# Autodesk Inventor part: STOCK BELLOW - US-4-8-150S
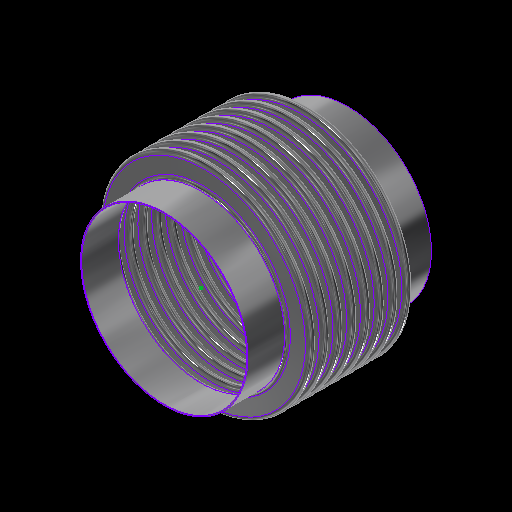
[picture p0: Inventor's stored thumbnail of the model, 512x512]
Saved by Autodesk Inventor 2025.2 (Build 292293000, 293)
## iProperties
Category: 22 GA (0.030 THICK)
RuleStatus: InUse
Created: 2024-01
Part Number: STOCK BELLOW - US-4-8-150S
Project: =STOCK BELLOWS: <Stock Number><SFILL>
Material: ASTM A240-304
Description: =STOCK BELLOWS: <Stock Number>, <SID_> I.D., <SOD_> O.D., <SPLY_> PLY, <Category>, <SNET_CONS> CONS.<PITCH_><STANGENT_> TANGENT<SFILL>
Document SubType Name: Sheet Metal
Designer: GS
Stock Number: U.S-4-8-150S
Surface Area: 2717.32 cm^2
Volume: 102.9 cm^3
Sheet Metal Rule: Default
Appearance: STAINLESS STEEL
Mass: 829.096 g
Density: 8.05729 g/cm^3
THK: 0.036
ID: 3.500
OD: 4.250
CONS_: 2
PITCH: 0.500
TANGENT: 0.500
BELLOWS_UPSET: 0.000
d79: 1.000
d82: 1.000
d83: 26.000
d84: 24.000
d174: 8
d214: 8
STHK_: 0.030
SID_: 4.500
SOD_: 5.750
SPITCH_: 0.375
STANGENT__: 1.000
SBELLOWS_UPSET_: 0.000
SDIFF_TAN: 1.000
d252: 2
d275: 2
d287: 0.050
d289: 0.500
d290: 0.000
SOD_NECK: 4 9/16
PLY: 1
PSET: 4.178
PBAR: 1.035
COUNTER: 1.500
NET_TUBE: 3.071
CONS: 2
S_CONS: 0
NET_CONS: 2
ID_M: 88.90 mm
OD_M: 107.95 mm
THK_M: 0.91 mm
ID_U: 3.500 in
OD_U: 4.250 in
THK_U: 0.036 in
TANGENT2: 0.500
TAN_TO_TAN: 1.000 in
d80: 2.571
d81: 10
SID: 2.375
SCONS_: 8
SPITCH: 0.250
STANGENT_: 1.000
SBELLOWS_UPSET: 0.000
SNET_CONS: 8
SS_CONS: 0
SCONS: 8
d190: 8
d191: 1
d192: 1
d193: 8
d194: 0
SIZE: 4.00
PRESSURE: 150
d230: 8
STANGENT: 4.000
SPLY_: 1
d233: 8
d234: 0
d263: 2
d265: 1
d268: 2
d269: 0
d286: 2
d288: 1
d291: 2
d292: 0
SREROLL: 0.750
BLETP: 0.000 ul
PRES_Copy: 85
MATTABLE: 20 GA (0.036 THICK)
PART_NUMBER: U.S-4-8-150S
PITCH_: =, <SPITCH_> PITCH,
CFILL: .
SFILL: .
MESH: ,
COMP: 0.7
EXT: 0.35
LAT: 0.13
ANG: 573
ASR: 1224
LSR: 4822
ANSR: 63
PRES: 150
COMPM: 7.0
EXTM: 3.5
LATM: 1.30
ASRM: 214.359
PRESM: 10.342
LSRM: 844.477
ANSRM: 11.033
TEMPMIN: 20
TEMPMAX: 800
TEMPMINM: -7
TEMPMAXM: 427
WEIGHTM: 0.829
WEIGHT: 1.828
Author: GS
Keywords: 20 GA (0.036 THICK)
Comments: =STOCK BELLOW - <STOCK NUMBER>
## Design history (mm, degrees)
sketch "Sketch2"
  geometry: L1 (0, -177.245)-(0, 562.856) reference; L2 (45.364, 0)-(44.45, 0); L3 (48.082, -2.718)-(50.343, -2.718); L4 (48.082, -3.632)-(50.343, -3.632); L5 (50.343, -9.982)-(48.082, -9.982); L6 (50.343, -9.068)-(48.082, -9.068); L7 (45.364, -12.7)-(44.45, -12.7); L8 (48.082, 0)-(48.082, -12.7); L9 (50.343, -6.35)-(53.975, -6.35); L10 (44.45, 0)-(44.45, -12.7); L11 (20.376, 102.841)-(20.376, 101.926); L12 (58.262, 457.127)-(58.262, 349.177); L13 (58.262, 444.427)-(58.262, 336.477); L14 (93.133, -58.817)-(93.133, -71.517); L15 (118.746, -66.401)-(118.746, -66.401); L16 (50.343, -9.068)-(50.343, -9.982); L17 (48.082, -9.068)-(48.082, -9.982); L18 (48.082, -9.525)-(50.343, -9.525); L19 (53.975, 0)-(53.975, -12.7); L20 (-50.343, -9.068)-(-50.343, -9.982); L21 (-50.343, -2.718)-(-48.082, -2.718); L22 (-50.343, -3.632)-(-48.082, -3.632); L23 (-48.082, -9.068)-(-50.343, -9.068); L24 (-50.343, -9.525)-(-48.082, -9.525); L25 (-48.082, -9.982)-(-50.343, -9.982); L26 (-48.082, -9.068)-(-48.082, -9.982); L27 (-44.45, 0.653)-(-44.45, -12.047); L28 (-48.082, -6.35)-(-44.45, -6.35); L29 (-50.343, 0.653)-(-50.343, -12.7); L30 (-53.061, 0)-(-53.975, 0); L31 (-53.975, 0)-(-53.975, -12.7); L32 (-53.061, -12.7)-(-53.975, -12.7); A1 r 2.718 centre (48.082, 0) between (45.364, 0) and (48.082, -2.718); A2 r 3.632 centre (48.082, 0) between (44.45, 0) and (48.082, -3.632); A3 r 3.632 centre (50.343, -6.35) between (50.343, -9.982) and (50.343, -2.718); A4 r 2.718 centre (50.343, -6.35) between (50.343, -9.068) and (50.343, -3.632); A5 r 2.718 centre (48.082, -12.7) between (48.082, -9.982) and (45.364, -12.7); A6 r 3.632 centre (48.082, -12.7) between (48.082, -9.068) and (44.45, -12.7); A7 r 3.175 centre (50.343, -6.35) between (50.343, -9.525) and (53.518, -6.35); A8 r 3.175 centre (48.082, -12.7) between (48.082, -9.525) and (44.907, -12.7); A9 r 2.718 centre (-50.343, -12.7) between (-50.343, -9.982) and (-53.061, -12.7); A10 r 2.718 centre (-48.082, -6.35) between (-48.082, -9.068) and (-48.082, -3.632); A11 r 3.175 centre (-48.082, -6.35) between (-48.082, -9.525) and (-44.907, -6.35); A12 r 3.632 centre (-48.082, -6.35) between (-48.082, -9.982) and (-48.082, -2.718); A13 r 3.175 centre (-50.343, -12.7) between (-50.343, -9.525) and (-53.518, -12.7); A14 r 3.632 centre (-50.343, -12.7) between (-50.343, -9.068) and (-53.975, -12.7); A15 r 2.718 centre (-50.343, 0) between (-53.061, 0) and (-50.343, -2.718); A16 r 3.632 centre (-50.343, 0) between (-53.975, 0) and (-50.343, -3.632); 10 further points
  constraints: 62 end point, 38 point on circle, 20 tangent, 16 centre point, 12 parallel, 9 midpoint, 7 vertical, 6 coincident, 6 concentric, 6 point on line, 4 equal radius, 4 perpendicular, 3 horizontal, 1 collinear, 1 horizontal alignment, 10 other
  dimensions: "THK" = 0.9144 distance of L11.start L11.end; "ID" = 88.9 distance of L11.end point (20.376, 13.026); "OD" = 107.95 distance of L12.start L12.end; "PITCH" = 12.7 distance of L12.start L13.start; "TANGENT" = 12.7 distance of L14.start L14.end; "BELLOWS_UPSET" = 0 distance of L15.start L15.end; "d43" = 88.9 diameter of L10 L1 (= ID); "d44" = 107.95 diameter of L9.end L1 (= OD); "d45" = 0.9144 distance between parallel lines of L5 L6 (computed from THK, PLY); "d46" = 3.6322 radius of A3 (computed from PITCH, THK, PLY); "UPSET_PITCH" = 12.7 distance of L2.end L7.end (derived); "SIDEWALL_ANGLE" = 360 deg dimension on L3 L9 (derived); "CON_GAP" = 5.4356 distance of point (48.082, -9.068) point (48.082, -3.632) (derived); "TAN1" = 4.98728 dimension on A8 (derived); "TAN2" = 4.98728 dimension on A7 (derived); "LEG1" = 2.2606 distance of L18.start L18.end (derived); "d278" = 0.9144 distance between parallel lines of L25 L23 (derived); "d279" = 3.6322 radius of A12 (derived); "d280" = 12.7 distance of L30.end L31.end (derived); "d281" = 360 deg dimension on L21 L28 (derived); "d282" = 5.4356 distance of point (-50.343, -9.068) point (-50.343, -3.632) (derived); "d283" = 4.98728 dimension on A13 (derived); "d284" = 4.98728 dimension on A11 (derived); "d285" = 2.2606 distance of L24.start L24.end (derived); "d293" = 88.9 diameter of L27 L1 (derived); "d294" = 107.95 diameter of L31 L1 (derived)
  node "Sketch Rectangular Pattern1" dims "d31" = 25.4, "ID" = 88.9
  node "Sketch Rectangular Pattern2" dims "d39" = 25.4, "PITCH" = 12.7
revolve "CONS" stored, may be unused: angle "d48" = 90 deg
node "BELLOW MIDPLANE"
pattern_linear "Rectangular Pattern2" dims "d52" = 12.7 (= UPSET_PITCH)
sketch "Sketch5"
  geometry: C1 r 45.364 at (0, 0) reference; C2 r 44.45 at (0, 0) reference
extrude "TANGENT" new body sketch "Sketch5" distance "d53" = 12.7 (= TANGENT); taper "d54" = 0 deg
revolve "SAMETAN" stored, may be unused: angle "d65" = 90 deg
revolve "DIFFTAN" stored, may be unused: angle "d70" = 90 deg
sketch "Sketch9"
  geometry: L1 (53.319, 0)-(-53.319, 0) reference; L2 (0, -17.78)-(0, 17.78) reference; L3 (38.085, 0)-(-38.085, 0); L4 (38.085, -11.906)-(38.085, 11.906); L5 (25.385, -11.906)-(25.385, 11.906); L6 (13.15, 11.906)-(13.15, -11.906); L7 (-25.385, -11.906)-(-25.385, 11.906); L8 (-38.085, -11.906)-(-38.085, 11.906); L9 (37.291, -11.906)-(37.291, 11.906); L10 (38.085, -11.906)-(37.291, -11.906); L11 (38.085, 11.906)-(37.291, 11.906); L12 (13.546, 11.906)-(12.753, 11.906); L13 (12.753, 11.906)-(12.753, -11.906); L14 (12.753, -11.906)-(13.546, -11.906); L15 (13.546, -11.906)-(13.546, 11.906); L16 (-13.546, 11.906)-(-13.546, -11.906); L17 (-13.15, 11.906)-(-13.15, -11.906); L18 (-13.546, -11.906)-(-12.753, -11.906); L19 (-12.753, -11.906)-(-12.753, 11.906); L20 (-12.753, 11.906)-(-13.546, 11.906); L21 (-38.085, -11.906)-(-37.291, -11.906); L22 (-37.291, -11.906)-(-37.291, 11.906); L23 (-37.291, 11.906)-(-38.085, 11.906); L24 (-38.085, 11.906)-(-38.085, -11.906); L25 (38.085, -0.397)-(-38.085, -0.397); L26 (-38.085, -0.397)-(-38.085, 0.397); L27 (-38.085, 0.397)-(38.085, 0.397); L28 (38.085, 0.397)-(38.085, -0.397); L29 (-38.085, 11.906)-(38.085, 11.906); L30 (38.085, 11.906)-(38.085, 12.7); L31 (38.085, 12.7)-(-38.085, 12.7); L32 (-38.085, 12.7)-(-38.085, 11.906); L33 (38.085, -11.906)-(-38.085, -11.906); L34 (-38.085, -11.906)-(-38.085, -12.7); L35 (-38.085, -12.7)-(38.085, -12.7); L36 (38.085, -12.7)-(38.085, -11.906); 30 further points
  constraints: 68 end point, 13 midpoint, 13 parallel, 8 horizontal, 7 perpendicular, 6 equal length, 3 point on line, 2 vertical, 14 other
  dimensions: "d115" = 23.8125 distance of L4.start L4.end (derived); "d116" = 12.7 distance between parallel lines of L4 L5 (derived); "d117" = 12.23516 distance between parallel lines of L5 L6 (derived); "d125" = 38.53427 distance between parallel lines of L7 L6 (derived); "d127" = 12.7 distance between parallel lines of L8 L7 (derived); "d128" = 24.93516 distance between parallel lines of L6 L4 (derived); "d130" = 76.16943 distance between parallel lines of L8 L4 (derived); "RULER_THK" = 0.79375 distance between parallel lines of L4 L9; "d135" = 0.79375 distance of L13.end L14.end (derived); "d138" = 26.29911 distance of L13.end L16.end (derived); "d143" = 0.79375 distance of L22.end L8.end (derived); "d144" = 0.79375 distance between parallel lines of L27 L25 (derived)
extrude "RULER" join sketch "Sketch9" distance "d149" = 0.79375 (derived); taper "d150" = 0 deg
extrude "BARS" join sketch "Sketch9" distance "d151" = 0.79375 (derived); taper "d152" = 0 deg
pattern_linear "Rectangular Pattern4" dims "d155" = 26.29911 (derived)
sketch "Sketch13"
  geometry: L1 (93.149, -52.467)-(93.149, -77.867); L2 (57.912, 0)-(57.15, 0); L3 (57.912, -9.525)-(57.15, -9.525); L4 (70.263, -7.525)-(59.912, -7.525); L5 (70.263, -6.763)-(59.912, -6.763); L6 (70.263, -4.763)-(73.025, -4.763); L7 (59.912, -2)-(70.263, -2); L8 (59.912, 0)-(59.912, -9.525); L9 (57.15, 0)-(57.15, -9.525); L10 (58.254, -350.381)-(58.254, -496.431); L11 (58.254, -359.906)-(58.254, -505.956); L12 (58.254, -378.956)-(58.254, -525.006); L13 (58.254, -388.481)-(58.254, -534.531); L14 (58.254, -398.006)-(58.254, -544.056); L15 (58.254, -407.531)-(58.254, -553.581); L16 (58.254, -417.056)-(58.254, -563.106); L17 (58.254, -369.431)-(58.254, -515.481); L18 (20.376, 102.688)-(20.376, 101.926); L19 (59.912, -2.762)-(70.263, -2.762); L20 (0, -696.265)-(0, 235.847) reference; L21 (-23.752, 0)-(142.514, 0) reference; A1 r 2 centre (59.912, 0) between (57.912, 0) and (59.912, -2); A2 r 2 centre (59.912, -9.525) between (59.912, -7.525) and (57.912, -9.525); A3 r 2.762 centre (59.912, -9.525) between (59.912, -6.763) and (57.15, -9.525); A4 r 2 centre (70.263, -4.763) between (70.263, -6.763) and (70.263, -2.762); A5 r 2.762 centre (70.263, -4.763) between (70.263, -7.525) and (70.263, -2); A6 r 2.762 centre (59.912, 0) between (57.15, 0) and (59.912, -2.762); 6 further points; 1 other entity
  constraints: 38 end point, 15 point on circle, 9 tangent, 6 centre point, 6 parallel, 5 vertical alignment, 4 point on line, 4 vertical, 3 coincident, 3 concentric, 2 collinear, 2 equal radius, 1 horizontal, 1 perpendicular, 23 other
  dimensions: "SBELLOWS_UPSET_" = 0 distance of point (118.762, -66.401) point (118.762, -66.401); "STOTAL_THK_BELLOW__" = 0.762 distance between parallel lines of L4 L5 (derived); "d224" = 2.76225 radius of A5 (derived); "d225" = 9.525 distance of L2.end L3.end (derived); "SSIDEWALL_ANGLE_" = 360 deg dimension on L7 L6 (derived); "SSCON_GAP_" = 4.0005 distance of point (59.912, -6.763) point (59.912, -2.762) (derived); "d235" = 114.3 diameter of L9 L20 (derived); "d236" = 146.05 diameter of L6.end L20 (derived)
  node "Sketch Rectangular Pattern4" dims "d228" = 25.4
  node "Sketch Rectangular Pattern5" dims "d229" = 25.4
revolve "SBELLOW" stored, may be unused: angle "d197" = 90 deg
pattern_linear "Rectangular Pattern5" dims "d204" = 9.525 (derived)
revolve "STANGENT" stored, may be unused: angle "d240" = 90 deg
revolve "SSAMETAN" stored, may be unused: angle "d241" = 90 deg
revolve "SDIFFTAN" stored, may be unused: angle "d246" = 90 deg
revolve "INVCON" stored, may be unused: angle "d295" = 90 deg
pattern_linear "Rectangular Pattern6" dims "d298" = 12.7 (derived)
revolve "INVTANGENT" stored, may be unused: angle "d302" = 90 deg
revolve "INVSAMETAN" stored, may be unused: angle "d307" = 90 deg
revolve "INVDIFFTAN" stored, may be unused: angle "d312" = 90 deg
sketch "ID BELLOW MOUNT CALC"
  geometry: L1 (44.45, 0)-(38.1, 0); L2 (38.1, 0)-(38.1, 12.7); L3 (38.1, 12.7)-(44.45, 12.7); L4 (44.45, 12.7)-(44.45, 0); L5 (36.513, 12.7)-(35.598, 12.7); L6 (35.598, 12.7)-(35.598, 0); L7 (35.598, 0)-(36.513, 0); L8 (36.513, 0)-(36.513, 12.7); L9 (0, -2.54)-(0, 15.24) reference; L10 (-8.89, 0)-(53.34, 0) reference; 1 further point
  constraints: 16 end point, 5 parallel, 2 collinear, 2 horizontal, 2 perpendicular
  dimensions: "d314" = 12.7 distance of L5.end L6.end (derived); "d315" = 0.9144 distance of L5.start L5.end (derived); "IG" = 1.5875 distance between parallel lines of L2 L8; "PIPE_OD" = 88.9 diameter of L4 L9; "PIPE_WALL" = 6.35 distance of L2.end L3.end; "ID_MT_BELLOW" = 71.1962 diameter of L6 L9 (derived)
revolve "CFILL" stored, may be unused: angle "d320" = 90 deg
pattern_linear "Rectangular Pattern7" dims "d323" = 12.7 (derived)
revolve "SFILL" stored, may be unused: angle "d324" = 90 deg
pattern_linear "Rectangular Pattern8" dims "d327" = 9.525 (derived)
node "STOCK BELLOW MIDPLANE"
node "BELLOW"
sketch "Sketch6"
  geometry: L1 (-12.7, 45.364)-(0, 45.364); L2 (0, 45.364)-(0, 44.45); L3 (0, 44.45)-(-12.7, 44.45); L4 (-12.7, 44.45)-(-12.7, 45.364); L5 (10.16, 0)-(-60.96, 0) reference; L6 (-38.1, -89.422)-(-38.1, 153.44) reference; 1 further point
  constraints: 8 end point, 2 parallel, 1 horizontal, 1 perpendicular
  dimensions: "d61" = 12.7 distance of L2.end L3.end (derived); "d62" = 0.9144 distance of L1.end L2.end (derived); "d63" = 88.9 diameter of L3 L5 (derived); "d64" = 25.4 distance between parallel lines of L4 L6 (derived)
sketch "Sketch12"
  geometry: 1 further point
sketch "Sketch14"
  geometry: L1 (-25.4, 57.912)-(0, 57.912); L2 (0, 57.912)-(0, 57.15); L3 (0, 57.15)-(-25.4, 57.15); L4 (-25.4, 57.15)-(-25.4, 57.912); L5 (5.08, 0)-(-30.48, 0) reference; L6 (0, -11.582)-(0, 69.494) reference; 1 further point
  constraints: 8 end point, 2 parallel, 1 collinear, 1 horizontal, 1 perpendicular
  dimensions: "d237" = 0.762 distance of L3.end L1.start (derived); "d238" = 114.3 diameter of L3 L5 (derived); "d239" = 25.4 distance of L1.start L1.end (derived); "SOD_NECK" = 115.824 diameter of L1 L5 (derived)
sketch "Sketch15"
  geometry: L1 (-11.582, 0)-(69.494, 0) reference; L2 (57.15, -76.2)-(57.912, -76.2); L3 (57.912, -76.2)-(57.912, -101.6); L4 (57.912, -101.6)-(57.15, -101.6); L5 (57.15, -101.6)-(57.15, -76.2); L6 (0, -124.46)-(0, 35.56) reference; 1 further point
  constraints: 8 end point, 2 parallel, 1 horizontal, 1 perpendicular
  dimensions: "d205" = 25.4 distance of L4.end L2.start (derived); "d206" = 0.762 distance of L3.end L4.end (derived); "d207" = 114.3 diameter of L5 L6 (derived); "d208" = 76.2 distance between parallel lines of L1 L2 (derived)
node "TANGENT_"
node "SAME_TAN"
sketch "Sketch8"
  geometry: L1 (45.364, -25.4)-(44.45, -25.4); L2 (44.45, -25.4)-(44.45, -38.1); L3 (44.45, -38.1)-(45.364, -38.1); L4 (45.364, -38.1)-(45.364, -25.4); L5 (0, -48.26)-(0, 22.86) reference; L6 (-89.422, 0)-(153.44, 0) reference; 1 further point
  constraints: 8 end point, 2 parallel, 1 horizontal, 1 perpendicular
  dimensions: "d66" = 88.9 diameter of L2 L5 (derived); "TOTAL_THK_BELLOW" = 0.9144 distance of L2.end L3.end (derived); "d68" = 25.4 distance between parallel lines of L1 L6 (derived); "d69" = 12.7 distance of L1.end L2.end (derived)
node "DIFF_TAN"
node "Sketch Rectangular Pattern3" dims "d138" = 26.29911 (derived), "d141" = 25.4
node "SBELLOW_"
node "STANGENT_"
node "SSAME_TAN"
sketch "Sketch16"
  geometry: L1 (57.912, -76.2)-(57.15, -76.2); L2 (57.15, -76.2)-(57.15, -101.6); L3 (57.15, -101.6)-(57.912, -101.6); L4 (57.912, -101.6)-(57.912, -76.2); L5 (0, -124.46)-(0, 35.56) reference; L6 (-11.582, 0)-(69.494, 0) reference; 1 further point
  constraints: 8 end point, 2 parallel, 1 horizontal, 1 perpendicular
  dimensions: "SDIFF_TAN" = 25.4 distance of L3.end L1.start; "d243" = 0.762 distance of L2.end L3.end (derived); "d244" = 76.2 distance between parallel lines of L1 L6 (derived); "d245" = 114.3 diameter of L2 L5 (derived)
node "SDIFF_TAN"
body "Solid15"
sketch "Sketch17"
  geometry: L1 (53.975, 12.7)-(53.061, 12.7); L2 (53.061, 12.7)-(53.061, 0); L3 (53.061, 0)-(53.975, 0); L4 (53.975, 0)-(53.975, 12.7); L5 (0, -2.54)-(0, 15.24) reference; L6 (-10.795, 0)-(64.77, 0) reference; 2 further points
  constraints: 8 end point, 2 parallel, 1 horizontal, 1 midpoint, 1 perpendicular, 1 point on line
  dimensions: "INVTANGENT" = 12.7 distance of L3.end L1.start (derived); "d300" = 0.9144 distance of L1.start L1.end (derived); "d301" = 107.95 diameter of L4 L5 (derived)
body "Solid16"
sketch "Sketch18"
  geometry: L1 (53.975, -25.4)-(53.061, -25.4); L2 (53.061, -25.4)-(53.061, -38.1); L3 (53.061, -38.1)-(53.975, -38.1); L4 (53.975, -38.1)-(53.975, -25.4); L5 (-10.795, 0)-(64.77, 0) reference; L6 (0, -48.26)-(0, 22.86) reference; 1 further point
  constraints: 8 end point, 2 parallel, 1 horizontal, 1 perpendicular
  dimensions: "d303" = 25.4 distance between parallel lines of L1 L5 (derived); "d304" = 12.7 distance of L3.end L1.start (derived); "d305" = 0.9144 distance of L2.end L3.end (derived); "d306" = 107.95 diameter of L4 L6 (derived)
body "Solid17"
sketch "Sketch19"
  geometry: L1 (53.975, -25.4)-(53.061, -25.4); L2 (53.061, -25.4)-(53.061, -38.1); L3 (53.061, -38.1)-(53.975, -38.1); L4 (53.975, -38.1)-(53.975, -25.4); L5 (0, -48.26)-(0, 22.86) reference; L6 (-10.795, 0)-(64.77, 0) reference; 1 further point
  constraints: 8 end point, 2 parallel, 1 horizontal, 1 perpendicular
  dimensions: "d308" = 12.7 distance of L1.end L2.end (derived); "d309" = 107.95 diameter of L4 L5 (derived); "d310" = 0.9144 distance of L2.end L3.end (derived); "d311" = 25.4 distance between parallel lines of L1 L6 (derived)
body "Solid18"
body "Solid19"
body "Solid20"
other parameters: "BMPL" = -38.1, "PSET" = 106.1212 (computed from OD, THK, PLY) [user parameter], "PBAR" = 26.29911 (= 0.570796 x PITCH + OD - ID) [user parameter; used in 1 equation term], "COUNTER" = 15 [user parameter], "NET_TUBE" = 77.99823 (computed from CONS_, PBAR, TANGENT) [user parameter], "S_CONS" = 0 [user parameter; used in 1 equation term], "ID_M" = 88.9 (= ID) [user parameter], "OD_M" = 107.95 (= OD) [user parameter], "THK_M" = 0.9144 (= THK) [user parameter], "ID_U" = 88.9 (= ID) [user parameter], "OD_U" = 107.95 (= OD) [user parameter], "THK_U" = 0.9144 (= THK) [user parameter], "D_UNITS" = 0 [user parameter], "TANGENT2" = 12.7 [user parameter], "TAN_TO_TAN" = 25.4 [user parameter], "OD_NECK" = 90.7288 [user parameter], "d79" = 25.4, "d80" = 65.29823 [user parameter], "d82" = 25.4, "d83" = 660.4, "d84" = 609.6, "sa_0" = 4, "FRAME_THK" = 0.79375 [user parameter], "CON_FLAT" = 12.23516 [user parameter], "SID" = 60.325 [user parameter], "SPITCH" = 6.35 [user parameter], "STANGENT_" = 25.4 [user parameter], "SBELLOWS_UPSET" = 0 [user parameter], "SS_CONS" = 0 [user parameter], "STAN_TO_TAN_" = 76.2 [user parameter], "d100" = 0.762 [user parameter], "d191" = 25.4 [user parameter], "d194" = 0 [user parameter], "STANGENT" = 101.6 [user parameter], "d234" = 0 [user parameter], "SUPSET_PITCH_" = 9.525 [user parameter], "d269" = 0 [user parameter], "d287" = 1.27, "d289" = 12.7, "d290" = 0, "d292" = 0 [user parameter], "Thickness" = 3.048 (derived), "KFactor" = 4.4, "BendRadius" = 3.048 (derived), "BendReliefWidth" = 3.048 (derived), "BendReliefDepth" = 1.524 (derived), "CornerReliefSize" = 12.192 (derived), "SeamGap" = 0.00508, "MinimumRemnant" = 6.096 (derived), "TransitionRadius" = 3.048 (derived), "JacobiRadiusSize" = 3.048 (derived), "GapSize" = 3.048 (derived), "SREROLL" = 19.05 [user parameter], "CUR_STK_PITCH" = 9.525 [user parameter], "d328" = -38.1 (derived), "ASR" = 12240 [user parameter], "LSR" = 48220 [user parameter], "BLETP" = 0 [user parameter], "ASRM" = 2143.5912 [user parameter], "PRESM" = 103.41975 [user parameter], "LSRM" = 8444.7686 [user parameter], "ANSRM" = 110.3319 [user parameter], "TEMPMIN" = 2664.83333 [user parameter], "TEMPMAX" = 6998.16667 [user parameter], "TEMPMINM" = 2664.83333 [user parameter], "TEMPMAXM" = 6998.16667 [user parameter], "WEIGHT" = 8.29096 [user parameter], "WEIGHTM" = 0.00829 [user parameter]
